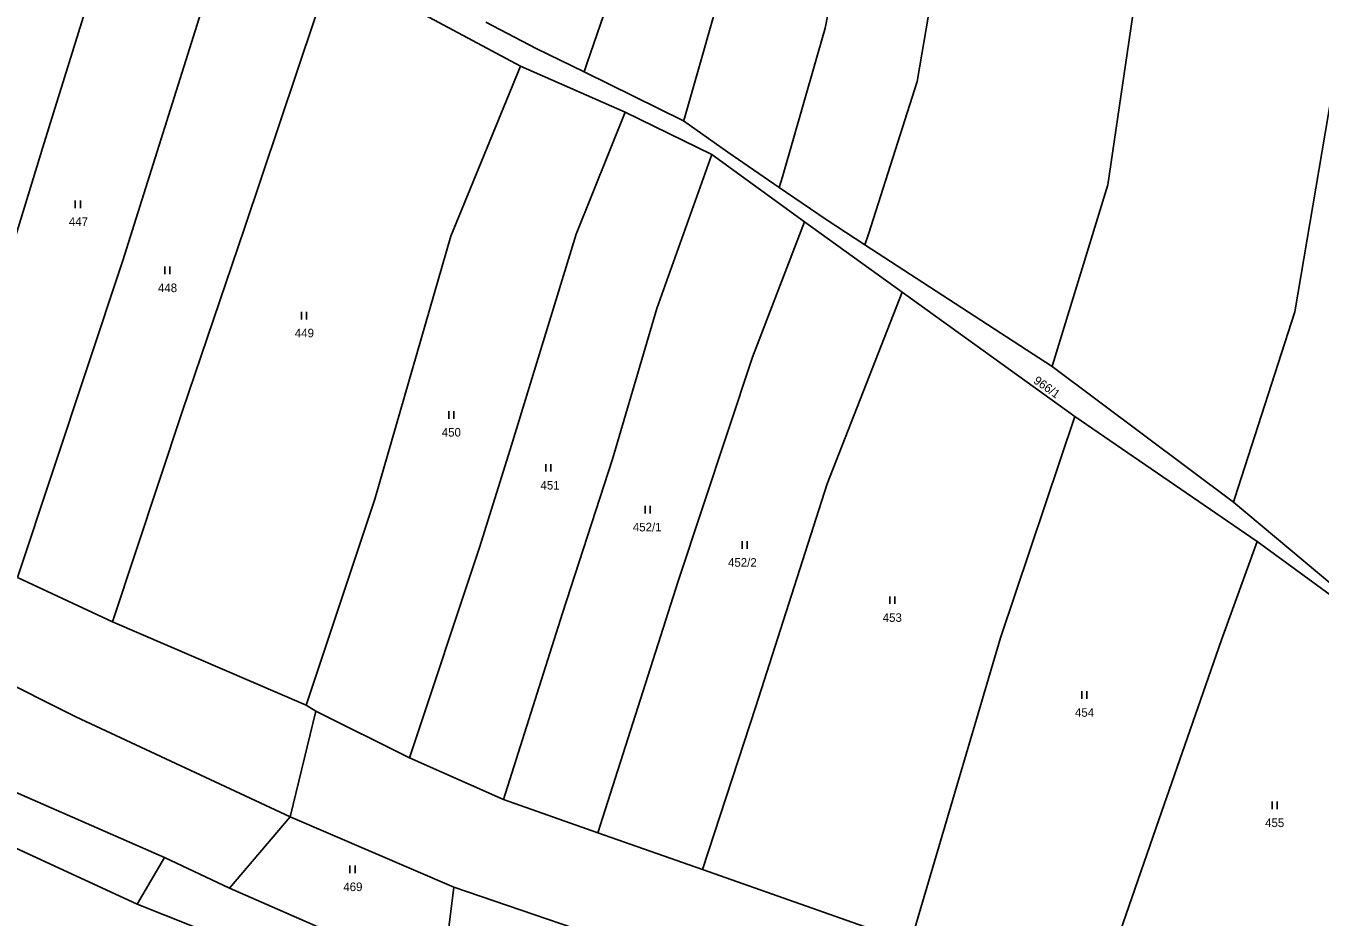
# Model space of a CAD drawing. Extents: x -751333 to -746055, y -1133395 to -1129777.
# Drawn here: x -748441 to -748184.6, y -1130603 to -1130426.4 of the extents above; entities that cross this region are included whole.
import ezdxf

# ---------------------------------------------------------------- set-up
doc = ezdxf.new("R2010")
doc.units = 0
for name, color, linetype in [('Hranice parcel', 7, 'Continuous'), ('Parcelní čísla', 7, 'Continuous'), ('Značky kultur', 7, 'Continuous')]:
    doc.layers.add(name, color=color, linetype=linetype)

msp = doc.modelspace()

# ---------------------------------------------------------------- linework, layer by layer
at = {"layer": 'Hranice parcel'}
for p, q in [((-748380.24, -1130414.38), (-748342.98, -1130434.33)), ((-748342.98, -1130434.33), (-748322.28, -1130443.45)), ((-748310.69, -1130445.15), (-748330.38, -1130435.49)), ((-748322.28, -1130443.45), (-748305.1, -1130451.81)), ((-748305.1, -1130451.81), (-748286.73, -1130465.15)), ((-748286.73, -1130465.15), (-748267.37, -1130479.15)), ((-748237.71, -1130493.88), (-748274.78, -1130469.75)), ((-748267.37, -1130479.15), (-748233.17, -1130503.73)), ((-748201.78, -1130520.76), (-748237.71, -1130493.88)), ((-748233.17, -1130503.73), (-748197.06, -1130528.56)), ((-748442.63, -1130535.63), (-748423.83, -1130544.43)), ((-748423.83, -1130544.43), (-748385.43, -1130560.99)), ((-748383.52, -1130562.14), (-748388.62, -1130583.11)), ((-748385.43, -1130560.99), (-748383.52, -1130562.14)), ((-748383.52, -1130562.14), (-748365.02, -1130571.43)), ((-748365.02, -1130571.43), (-748346.39, -1130579.64)), ((-748346.39, -1130579.64), (-748327.67, -1130586.29)), ((-748400.65, -1130597.24), (-748388.62, -1130583.11)), ((-748388.62, -1130583.11), (-748356.21, -1130597)), ((-748327.67, -1130586.29), (-748306.94, -1130593.5)), ((-748413.5, -1130591.12), (-748418.92, -1130600.37)), ((-748413.5, -1130591.12), (-748400.65, -1130597.24)), ((-748306.94, -1130593.5), (-748265.75, -1130608.04)), ((-748357.28, -1130605.56), (-748356.21, -1130597)), ((-748356.21, -1130597), (-748301.06, -1130615.84))]:
    msp.add_line(p, q, dxfattribs=at)
for points in [[(-748130.22, -1130087.61), (-748131.13, -1130105.98), (-748132.47, -1130123.43), (-748138.48, -1130165.82), (-748139.67, -1130175.32), (-748144.94, -1130218.98), (-748149.15, -1130242.84), (-748155.25, -1130281.49), (-748166.79, -1130346.74), (-748175.48, -1130397.01), (-748180.06, -1130426.59), (-748189.62, -1130483.05), (-748201.5, -1130519.88), (-748201.78, -1130520.76)], [(-748169.91, -1130092.32), (-748177.35, -1130147.37), (-748182.55, -1130189.99), (-748186.18, -1130220.14), (-748188.49, -1130234.32), (-748193.97, -1130267.58), (-748201.44, -1130315.33), (-748212.24, -1130367.23), (-748215.27, -1130383.11), (-748220.54, -1130416.01), (-748226.63, -1130457.88), (-748237.61, -1130493.57), (-748237.71, -1130493.88)], [(-748273.39, -1130097.24), (-748281.27, -1130156.73), (-748287.31, -1130202.54), (-748290.79, -1130232.85), (-748299.54, -1130289.08), (-748301.91, -1130302.35), (-748302.4, -1130309.37), (-748305.11, -1130326.61), (-748309.55, -1130348.99), (-748320.05, -1130405.29), (-748329.77, -1130433.7), (-748330.38, -1130435.49)], [(-748230.76, -1130101.5), (-748238.92, -1130155.41), (-748244.23, -1130193.64), (-748250.06, -1130231.72), (-748257.56, -1130283.34), (-748263.19, -1130320.1), (-748266.04, -1130338.03), (-748272.57, -1130374.93), (-748282.67, -1130426.83), (-748291.12, -1130456.26), (-748291.74, -1130458.41)], [(-748211.28, -1130100.51), (-748218.94, -1130146.82), (-748219.36, -1130157.24), (-748223.16, -1130188.85), (-748229.48, -1130229.5), (-748236.23, -1130271.46), (-748240.43, -1130308.77), (-748250.12, -1130359.49), (-748258.18, -1130400.55), (-748264.43, -1130437.38), (-748274.1, -1130467.62), (-748274.78, -1130469.75)], [(-748252.59, -1130102.61), (-748256.07, -1130126.15), (-748263.51, -1130176.19), (-748266.5, -1130195.5), (-748271.15, -1130229.91), (-748277.05, -1130270.85), (-748279.2, -1130292.94), (-748282.82, -1130314.7), (-748292.75, -1130368.29), (-748301.85, -1130414.23), (-748310.54, -1130444.61), (-748310.69, -1130445.15)], [(-748462.95, -1130526.39), (-748452.24, -1130498.41), (-748444.7, -1130473.49), (-748437.34, -1130449.55), (-748416.99, -1130383.85)], [(-748442.63, -1130535.63), (-748421.81, -1130472.84), (-748398.74, -1130399.57)], [(-748423.83, -1130544.43), (-748409.99, -1130502.63), (-748397.69, -1130466.45), (-748380.24, -1130414.38)], [(-748330.38, -1130435.49), (-748339.87, -1130430.84), (-748349.86, -1130425.63)], [(-748385.43, -1130560.99), (-748371.83, -1130520.13), (-748356.78, -1130467.99), (-748342.98, -1130434.33)], [(-748365.02, -1130571.43), (-748351.1, -1130529.74), (-748345.06, -1130510.33), (-748332.01, -1130467.6), (-748322.28, -1130443.45)], [(-748291.74, -1130458.41), (-748301.96, -1130451.39), (-748310.69, -1130445.15)], [(-748346.39, -1130579.64), (-748334.71, -1130542.76), (-748324.77, -1130512.21), (-748315.97, -1130482.36), (-748305.1, -1130451.81)], [(-748274.78, -1130469.75), (-748282.46, -1130464.75), (-748291.74, -1130458.41)], [(-748327.67, -1130586.29), (-748311.77, -1130536.36), (-748297.02, -1130491.98), (-748286.73, -1130465.15)], [(-748306.94, -1130593.5), (-748296.39, -1130561.23), (-748282.24, -1130517.07), (-748267.37, -1130479.15)], [(-748265.75, -1130608.04), (-748247.9, -1130547.61), (-748233.17, -1130503.73)], [(-748526.29, -1130515.48), (-748486.84, -1130536.66), (-748470.75, -1130543.61), (-748464.43, -1130546.57), (-748431.07, -1130563.27), (-748388.62, -1130583.11)], [(-748162.54, -1130550.9), (-748179.44, -1130539.41), (-748201.78, -1130520.76)], [(-748229.57, -1130621.28), (-748216.56, -1130583.68), (-748204.16, -1130547.99), (-748197.06, -1130528.56)], [(-748197.06, -1130528.56), (-748178.46, -1130542.16), (-748161.77, -1130554.58)], [(-748516.42, -1130541.69), (-748493.99, -1130554.85), (-748454.25, -1130573.29), (-748413.5, -1130591.12)], [(-748511.31, -1130555.77), (-748507.24, -1130559.45), (-748489.41, -1130567.71), (-748456.16, -1130583.21), (-748418.92, -1130600.37)], [(-748400.65, -1130597.24), (-748378.93, -1130606.77), (-748358.56, -1130614.59)], [(-748418.92, -1130600.37), (-748345.69, -1130629.51), (-748298.06, -1130647.31)]]:
    msp.add_lwpolyline(points, dxfattribs=at)
at = {"layer": 'Značky kultur'}
for p, q in [((-748431.191, -1130462.45), (-748431.191, -1130460.95)), ((-748430.19, -1130462.45), (-748430.19, -1130460.95)), ((-748413.491, -1130475.56), (-748413.491, -1130474.06)), ((-748412.49, -1130475.56), (-748412.49, -1130474.06)), ((-748386.391, -1130484.52), (-748386.391, -1130483.02)), ((-748385.39, -1130484.52), (-748385.39, -1130483.02)), ((-748357.221, -1130504.19), (-748357.221, -1130502.69)), ((-748356.22, -1130504.19), (-748356.22, -1130502.69)), ((-748338.001, -1130514.68), (-748338.001, -1130513.18)), ((-748337, -1130514.68), (-748337, -1130513.18)), ((-748318.331, -1130522.98), (-748318.331, -1130521.48)), ((-748317.33, -1130522.98), (-748317.33, -1130521.48)), ((-748299.111, -1130529.98), (-748299.111, -1130528.48)), ((-748298.11, -1130529.98), (-748298.11, -1130528.48)), ((-748269.831, -1130540.91), (-748269.831, -1130539.41)), ((-748268.83, -1130540.91), (-748268.83, -1130539.41)), ((-748231.811, -1130559.71), (-748231.811, -1130558.21)), ((-748230.81, -1130559.71), (-748230.81, -1130558.21)), ((-748194.111, -1130581.57), (-748194.111, -1130580.07)), ((-748193.11, -1130581.57), (-748193.11, -1130580.07)), ((-748376.781, -1130594.26), (-748376.781, -1130592.76)), ((-748375.78, -1130594.26), (-748375.78, -1130592.76))]:
    msp.add_line(p, q, dxfattribs=at)

# ---------------------------------------------------------------- texts
at = {"layer": 'Parcelní čísla'}
for s, p in [('447', (-748432.47, -1130466)), ('448', (-748414.82, -1130479.11)), ('449', (-748387.71, -1130488.07)), ('450', (-748358.6, -1130507.74)), ('451', (-748339.05, -1130518.23)), ('452/1', (-748320.75, -1130526.53)), ('452/2', (-748301.9, -1130533.53)), ('453', (-748271.26, -1130544.46)), ('454', (-748233.17, -1130563.26)), ('455', (-748195.51, -1130585.12)), ('469', (-748378.1, -1130597.81))]:
    msp.add_text(s, height=1.7, dxfattribs=at).set_placement(p)
msp.add_text('966/1', height=1.7, rotation=325, dxfattribs=at).set_placement((-748241.547, -1130496.996))

doc.saveas('drawing.dxf')
